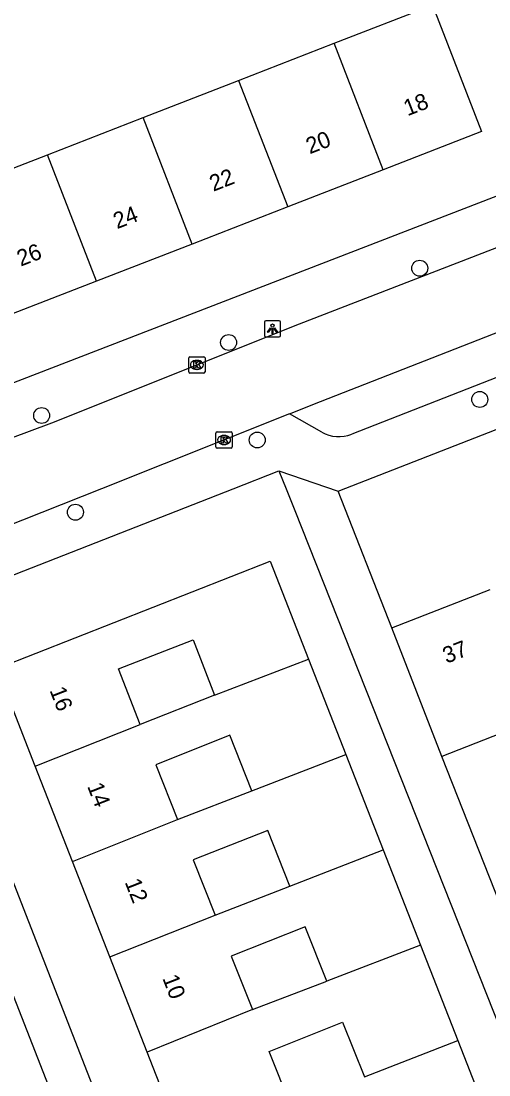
# Model space of a CAD drawing. Extents: x 159689 to 160786, y 387323 to 388339.
# Drawn here: x 160126.1 to 160154.9, y 387464 to 387528.7 of the extents above; entities that cross this region are included whole.
import ezdxf

# ---------------------------------------------------------------- set-up
doc = ezdxf.new("R2010")
doc.units = 0
for name, color, linetype in [('IMGEO_Boom', 7, 'Continuous'), ('IMGEO_Kolk', 7, 'Continuous'), ('IMGEO_Lichtpunt', 7, 'Continuous'), ('IMGEO_Pand', 7, 'Continuous'), ('IMGEO_Pand_nummerreeks', 7, 'Continuous'), ('IMGEO_Parkeervlak_open', 7, 'Continuous'), ('IMGEO_Rijbaan_lokaal_open', 7, 'Continuous'), ('IMGEO_Voetpad_open', 7, 'Continuous')]:
    doc.layers.add(name, color=color, linetype=linetype)

msp = doc.modelspace()

# ---------------------------------------------------------------- linework, layer by layer
at = {"layer": 'IMGEO_Boom'}
for centre in [(160150.636, 387513.548), (160138.89, 387508.986), (160154.327, 387505.486), (160127.399, 387504.499), (160140.65, 387502.993), (160129.476, 387498.555)]:
    msp.add_circle(centre, 0.489, dxfattribs=at)
at = {"layer": 'IMGEO_Kolk'}
for p, q in [((160136.439, 387507.181), (160136.439, 387508.033)), ((160136.514, 387508.107), (160137.366, 387508.107)), ((160136.927, 387507.887), (160136.952, 387507.887)), ((160137.44, 387508.033), (160137.44, 387507.181)), ((160136.95, 387507.327), (160136.925, 387507.327)), ((160137.366, 387507.107), (160136.514, 387507.107)), ((160138.112, 387502.569), (160138.112, 387503.421)), ((160138.187, 387503.495), (160139.039, 387503.495)), ((160138.6, 387503.275), (160138.625, 387503.275)), ((160139.113, 387503.421), (160139.113, 387502.569)), ((160138.623, 387502.715), (160138.598, 387502.715)), ((160139.039, 387502.495), (160138.187, 387502.495))]:
    msp.add_line(p, q, dxfattribs=at)
for points in [[(160136.439, 387507.181), (160136.439, 387508.033)], [(160136.514, 387508.107), (160137.366, 387508.107)], [(160136.76, 387507.807), (160136.883, 387507.807), (160136.883, 387507.656), (160137.013, 387507.807), (160137.177, 387507.807), (160137.031, 387507.656), (160137.184, 387507.407), (160137.032, 387507.407), (160136.947, 387507.571), (160136.883, 387507.504), (160136.883, 387507.407), (160136.76, 387507.407), (160136.76, 387507.807)], [(160137.44, 387508.033), (160137.44, 387507.181)], [(160137.366, 387507.107), (160136.514, 387507.107)], [(160138.112, 387502.569), (160138.112, 387503.421)], [(160138.187, 387503.495), (160139.039, 387503.495)], [(160139.113, 387503.421), (160139.113, 387502.569)], [(160138.433, 387503.195), (160138.556, 387503.195), (160138.556, 387503.044), (160138.686, 387503.195), (160138.85, 387503.195), (160138.704, 387503.044), (160138.857, 387502.795), (160138.705, 387502.795), (160138.62, 387502.959), (160138.556, 387502.892), (160138.556, 387502.795), (160138.433, 387502.795), (160138.433, 387503.195)], [(160139.039, 387502.495), (160138.187, 387502.495)]]:
    msp.add_lwpolyline(points, dxfattribs=at)
for centre, start, end in [((160136.516, 387508.031), 91.55205, 178.44795), ((160136.516, 387508.031), 91.55205, 178.44795), ((160137.364, 387508.031), 1.55205, 88.44795), ((160137.364, 387508.031), 1.55205, 88.44795), ((160136.516, 387507.183), 181.55205, 268.44795), ((160136.516, 387507.183), 181.55205, 268.44795), ((160137.364, 387507.183), 271.55205, 358.44795), ((160137.364, 387507.183), 271.55205, 358.44795), ((160138.189, 387503.419), 91.55205, 178.44795), ((160138.189, 387503.419), 91.55205, 178.44795), ((160139.037, 387503.419), 1.55205, 88.44795), ((160139.037, 387503.419), 1.55205, 88.44795), ((160138.189, 387502.571), 181.55205, 268.44795), ((160138.189, 387502.571), 181.55205, 268.44795), ((160139.037, 387502.571), 271.55205, 358.44795), ((160139.037, 387502.571), 271.55205, 358.44795)]:
    msp.add_arc(centre, 0.0765, start, end, dxfattribs=at)
for centre, major_axis, ratio, start_param, end_param in [((160136.926, 387507.607), (-0.387, 0.002), 0.722429, 4.712389, 7.853982), ((160136.951, 387507.607), (-0.39, 0.002), 0.717154, 1.570796, 4.712389), ((160138.599, 387502.995), (-0.387, 0.002), 0.722429, 4.712389, 7.853982), ((160138.624, 387502.995), (-0.39, 0.002), 0.717154, 1.570796, 4.712389)]:
    msp.add_ellipse(centre, major_axis=major_axis, ratio=ratio, start_param=start_param, end_param=end_param, dxfattribs=at)
at = {"layer": 'IMGEO_Lichtpunt'}
for p, q in [((160141.09, 387510.226), (160141.09, 387509.419)), ((160141.09, 387510.226), (160141.09, 387509.419)), ((160141.992, 387510.321), (160141.184, 387510.321)), ((160141.992, 387510.321), (160141.184, 387510.321)), ((160142.086, 387509.419), (160142.086, 387510.226)), ((160142.086, 387509.419), (160142.086, 387510.226)), ((160141.184, 387509.325), (160141.992, 387509.325)), ((160141.184, 387509.325), (160141.992, 387509.325))]:
    msp.add_line(p, q, dxfattribs=at)
for points in [[(160141.464, 387509.89), (160141.503, 387509.862), (160141.315, 387509.6), (160141.277, 387509.627), (160141.464, 387509.89)], [(160141.566, 387509.842), (160141.613, 387509.842), (160141.613, 387509.52), (160141.566, 387509.52), (160141.566, 387509.842)], [(160141.676, 387509.862), (160141.714, 387509.889), (160141.901, 387509.627), (160141.862, 387509.599), (160141.676, 387509.862)]]:
    msp.add_lwpolyline(points, dxfattribs=at)
msp.add_circle((160141.589, 387510.024), 0.0994, dxfattribs=at)
for centre, start, end in [((160141.184, 387510.226), 90, 180), ((160141.184, 387510.226), 90, 180), ((160141.992, 387510.226), 0, 90), ((160141.992, 387510.226), 0, 90), ((160141.184, 387509.419), 180, 270), ((160141.184, 387509.419), 180, 270), ((160141.992, 387509.419), 270, 0), ((160141.992, 387509.419), 270, 360)]:
    msp.add_arc(centre, 0.0946, start, end, dxfattribs=at)
at = {"layer": 'IMGEO_Pand'}
for points in [[(160145.375, 387527.371), (160151.419, 387529.721), (160154.439, 387521.952), (160148.394, 387519.602)], [(160139.503, 387525.088), (160145.375, 387527.371)], [(160148.394, 387519.602), (160145.375, 387527.371)], [(160133.631, 387522.805), (160139.503, 387525.088)], [(160139.503, 387525.088), (160142.523, 387517.319)], [(160127.758, 387520.522), (160133.631, 387522.805)], [(160136.651, 387515.036), (160133.631, 387522.805)], [(160121.887, 387518.239), (160127.758, 387520.522)], [(160130.778, 387512.753), (160127.758, 387520.522)], [(160148.394, 387519.602), (160142.523, 387517.319)], [(160142.523, 387517.319), (160136.651, 387515.036)], [(160136.651, 387515.036), (160130.778, 387512.753)], [(160130.778, 387512.753), (160124.906, 387510.47)], [(160127, 387482.94), (160124.641, 387488.961), (160141.44, 387495.541), (160143.798, 387489.52)], [(160148.917, 387491.449), (160154.962, 387493.803)], [(160151.994, 387483.546), (160148.917, 387491.449)], [(160133.461, 387485.52), (160132.132, 387488.926), (160136.702, 387490.709), (160138.031, 387487.303)], [(160138.031, 387487.303), (160143.798, 387489.52)], [(160143.798, 387489.52), (160146.092, 387483.664)], [(160138.031, 387487.303), (160133.461, 387485.52)], [(160158.039, 387485.9), (160156.654, 387485.361), (160151.994, 387483.546)], [(160127, 387482.94), (160133.461, 387485.52)], [(160140.323, 387481.442), (160138.97, 387484.848), (160134.408, 387483.036), (160135.742, 387479.678)], [(160140.323, 387481.442), (160146.092, 387483.664)], [(160146.092, 387483.664), (160148.386, 387477.808)], [(160129.293, 387477.084), (160127, 387482.94)], [(160135.742, 387479.678), (160140.323, 387481.442)], [(160129.293, 387477.084), (160135.742, 387479.678)], [(160142.653, 387475.576), (160141.311, 387478.995), (160136.719, 387477.192), (160138.057, 387473.786)], [(160142.653, 387475.576), (160148.386, 387477.808)], [(160148.386, 387477.808), (160150.68, 387471.953)], [(160131.587, 387471.228), (160129.293, 387477.084)], [(160138.057, 387473.786), (160142.653, 387475.576)], [(160131.587, 387471.228), (160138.057, 387473.786)], [(160144.924, 387469.741), (160143.594, 387473.077), (160139.052, 387471.266), (160140.359, 387467.987)], [(160150.68, 387471.953), (160144.924, 387469.741)], [(160150.68, 387471.953), (160152.973, 387466.097)], [(160133.881, 387465.372), (160131.587, 387471.228)], [(160140.359, 387467.987), (160144.924, 387469.741)], [(160140.359, 387467.987), (160133.881, 387465.372)], [(160142.713, 387462.078), (160141.382, 387465.418), (160145.899, 387467.219), (160147.24, 387463.854)], [(160147.24, 387463.854), (160152.973, 387466.097)], [(160152.973, 387466.097), (160154.412, 387462.423)], [(160136.175, 387459.517), (160133.881, 387465.372)]]:
    msp.add_lwpolyline(points, dxfattribs=at)
at = {"layer": 'IMGEO_Parkeervlak_open'}
msp.add_lwpolyline([(160122.056, 387484.978), (160133.798, 387454.894)], dxfattribs=at)
at = {"layer": 'IMGEO_Rijbaan_lokaal_open'}
for points in [[(160114.963, 387499.225), (160115.753, 387499.45), (160118.881, 387500.649), (160128.018, 387504.049), (160143.253, 387510.123), (160159.817, 387516.538)], [(160142.628, 387504.592), (160144.534, 387505.349), (160161.566, 387512.022)], [(160142.628, 387504.592), (160131.07, 387500), (160118.877, 387495.156), (160118.682, 387495.073)], [(160131.462, 387453.982), (160119.717, 387484.065)]]:
    msp.add_lwpolyline(points, dxfattribs=at)
at = {"layer": 'IMGEO_Voetpad_open'}
for points in [[(160145.626, 387499.854), (160204.532, 387522.83)], [(160113.221, 387501.712), (160160.319, 387519.908)], [(160162.493, 387509.628), (160146.454, 387503.345)], [(160144.614, 387503.473), (160142.628, 387504.592)], [(160120.792, 387492.803), (160139.164, 387500), (160141.985, 387501.105)], [(160141.985, 387501.105), (160145.626, 387499.854)], [(160141.985, 387501.105), (160142.423, 387500), (160142.953, 387498.663), (160156.933, 387463.411)], [(160148.917, 387491.449), (160145.626, 387499.854)], [(160156.541, 387472.034), (160151.994, 387483.546)]]:
    msp.add_lwpolyline(points, dxfattribs=at)
msp.add_arc((160145.669, 387505.35), 2.153, 240.66313, 291.37811, dxfattribs=at)

# ---------------------------------------------------------------- texts
at = {"layer": 'IMGEO_Pand_nummerreeks'}
for s, rotation, p in [('18', 21.24537, (160149.883, 387522.884)), ('20', 21.24537, (160143.878, 387520.549)), ('22', 21.24537, (160137.951, 387518.245)), ('24', 21.24537, (160132.033, 387515.944)), ('26', 21.24537, (160126.112, 387513.642)), ('37', 21.27631, (160152.283, 387489.24)), ('16', 291.39086, (160127.874, 387487.616)), ('14', 291.3883, (160130.185, 387481.719)), ('12', 291.3883, (160132.494, 387475.826)), ('10', 291.3883, (160134.806, 387469.923))]:
    msp.add_text(s, height=1, rotation=rotation, dxfattribs=at).set_placement(p)

doc.saveas('drawing.dxf')
